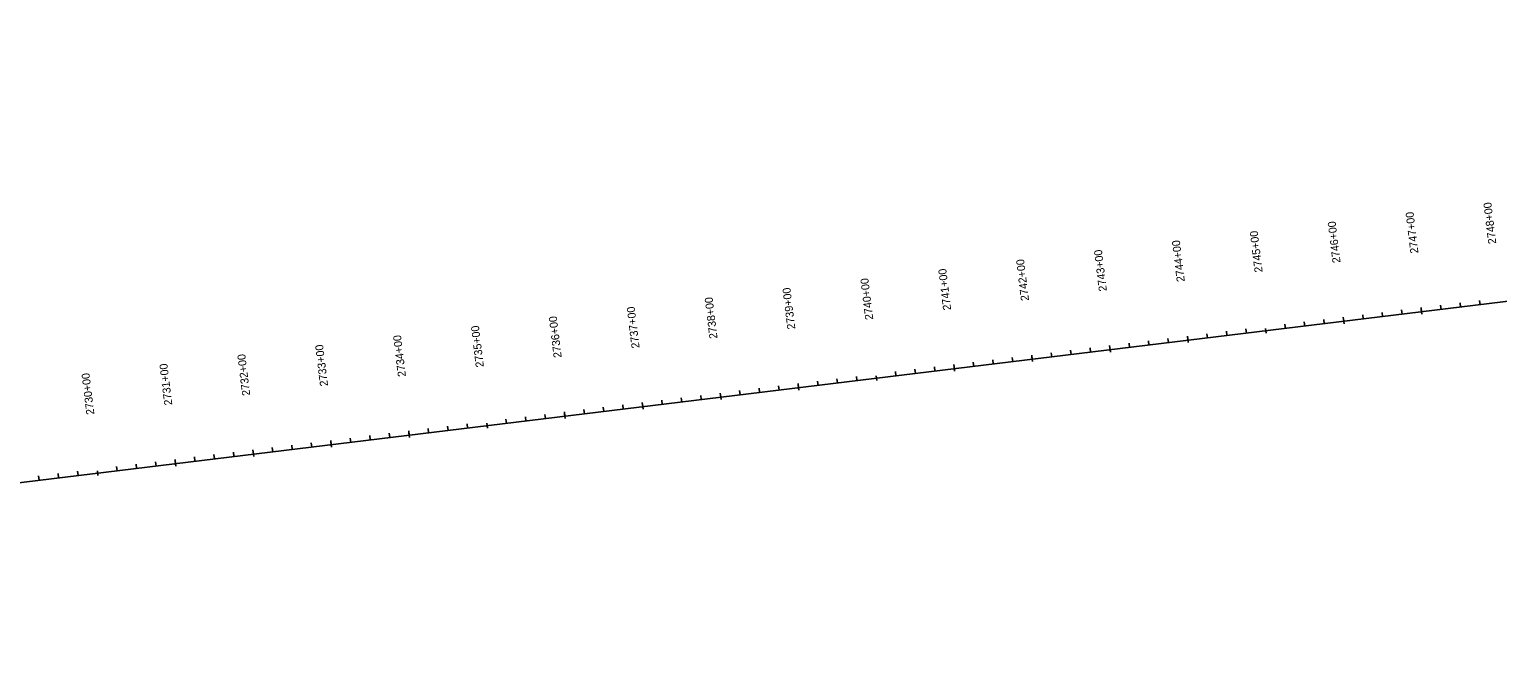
# Model space of a CAD drawing. Extents: x 18432127 to 18439586, y 7649485 to 7650472.
# Drawn here: x 18433981 to 18435853, y 7649488 to 7650289 of the extents above; entities that cross this region are included whole.
import ezdxf

# ---------------------------------------------------------------- set-up
doc = ezdxf.new("R2010")
doc.units = 0
for name, color, linetype in [('MeshTop', 7, 'Continuous'), ('Terrain', 7, 'Continuous'), ('TL_ShoulderTop', 7, 'Continuous')]:
    doc.layers.add(name, color=color, linetype=linetype)

msp = doc.modelspace()

# ---------------------------------------------------------------- linework, layer by layer
at = {"layer": 'MeshTop'}
for p, q in [((18435805.5, 7649934.7), (18435804.8, 7649940.1)), ((18435830.3, 7649937.7), (18435829.7, 7649943.2)), ((18435681.4, 7649919.6), (18435680.8, 7649925)), ((18435706.2, 7649922.6), (18435705.6, 7649928)), ((18435731.1, 7649925.6), (18435730.4, 7649931.1)), ((18435755.5, 7649931.7), (18435756.2, 7649925.6)), ((18435780.7, 7649931.7), (18435780, 7649937.1)), ((18435507.7, 7649898.4), (18435507.1, 7649903.9)), ((18435532.5, 7649901.5), (18435531.9, 7649906.9)), ((18435557, 7649907.5), (18435557.7, 7649901.4)), ((18435582.2, 7649907.5), (18435581.5, 7649912.9)), ((18435607, 7649910.5), (18435606.3, 7649916)), ((18435631.8, 7649913.6), (18435631.1, 7649919)), ((18435656.2, 7649919.6), (18435657, 7649913.5)), ((18435334, 7649877.3), (18435333.3, 7649882.7)), ((18435358.4, 7649883.3), (18435359.2, 7649877.3)), ((18435383.6, 7649883.3), (18435383, 7649888.7)), ((18435408.4, 7649886.3), (18435407.8, 7649891.8)), ((18435433.3, 7649889.4), (18435432.6, 7649894.8)), ((18435457.7, 7649895.4), (18435458.4, 7649889.4)), ((18435482.9, 7649895.4), (18435482.2, 7649900.8)), ((18435185.1, 7649859.1), (18435184.4, 7649864.5)), ((18435209.9, 7649862.2), (18435209.3, 7649867.6)), ((18435234.7, 7649865.2), (18435234.1, 7649870.6)), ((18435259.2, 7649871.2), (18435259.9, 7649865.2)), ((18435284.4, 7649871.2), (18435283.7, 7649876.6)), ((18435309.2, 7649874.2), (18435308.5, 7649879.7)), ((18435036.2, 7649841), (18435035.5, 7649846.4)), ((18435060.6, 7649847), (18435061.4, 7649841)), ((18435085.8, 7649847), (18435085.2, 7649852.5)), ((18435110.6, 7649850.1), (18435110, 7649855.5)), ((18435135.5, 7649853.1), (18435134.8, 7649858.5)), ((18435159.9, 7649859.1), (18435160.7, 7649853.1)), ((18434887.3, 7649822.8), (18434886.6, 7649828.3)), ((18434912.1, 7649825.9), (18434911.5, 7649831.3)), ((18434936.9, 7649828.9), (18434936.3, 7649834.3)), ((18434961.4, 7649835), (18434962.1, 7649828.9)), ((18434986.6, 7649834.9), (18434985.9, 7649840.4)), ((18435011.4, 7649838), (18435010.7, 7649843.4)), ((18434738.4, 7649804.7), (18434737.7, 7649810.1)), ((18434762.8, 7649810.8), (18434763.6, 7649804.7)), ((18434788, 7649810.7), (18434787.4, 7649816.2)), ((18434812.9, 7649813.8), (18434812.2, 7649819.2)), ((18434837.7, 7649816.8), (18434837, 7649822.2)), ((18434862.1, 7649822.9), (18434862.9, 7649816.8)), ((18434589.5, 7649786.6), (18434588.8, 7649792)), ((18434614.3, 7649789.6), (18434613.7, 7649795)), ((18434639.1, 7649792.6), (18434638.5, 7649798)), ((18434663.6, 7649798.7), (18434664.3, 7649792.6)), ((18434688.8, 7649798.7), (18434688.1, 7649804.1)), ((18434713.6, 7649801.7), (18434712.9, 7649807.1)), ((18434415.8, 7649765.4), (18434415.1, 7649770.8)), ((18434440.6, 7649768.4), (18434439.9, 7649773.8)), ((18434465, 7649774.5), (18434465.8, 7649768.4)), ((18434490.2, 7649774.5), (18434489.6, 7649779.9)), ((18434515.1, 7649777.5), (18434514.4, 7649782.9)), ((18434539.9, 7649780.5), (18434539.2, 7649785.9)), ((18434564.3, 7649786.6), (18434565.1, 7649780.5)), ((18434291.7, 7649750.3), (18434291, 7649755.7)), ((18434316.5, 7649753.3), (18434315.9, 7649758.7)), ((18434341.3, 7649756.3), (18434340.7, 7649761.7)), ((18434365.8, 7649762.4), (18434366.5, 7649756.3)), ((18434391, 7649762.4), (18434390.3, 7649767.8)), ((18434118, 7649729.1), (18434117.3, 7649734.5)), ((18434142.8, 7649732.1), (18434142.1, 7649737.5)), ((18434167.3, 7649738.2), (18434168, 7649732.1)), ((18434192.4, 7649738.2), (18434191.8, 7649743.6)), ((18434217.3, 7649741.2), (18434216.6, 7649746.6)), ((18434242.1, 7649744.2), (18434241.4, 7649749.6)), ((18434266.5, 7649750.3), (18434267.3, 7649744.2)), ((18433993.9, 7649714), (18433993.2, 7649719.4)), ((18434018.7, 7649717), (18434018.1, 7649722.4)), ((18434043.5, 7649720), (18434042.9, 7649725.5)), ((18434068, 7649726.1), (18434068.7, 7649720)), ((18434093.2, 7649726.1), (18434092.5, 7649731.5))]:
    msp.add_line(p, q, dxfattribs=at)
at = {"layer": 'Terrain'}
msp.add_line((18432137.1, 7649487.7), (18438712.4, 7650288.9), dxfattribs=at)
at = {"layer": 'TL_ShoulderTop'}
for p, q in [((18435656.6, 7649916.6), (18435655.9, 7649922)), ((18435755.9, 7649928.7), (18435755.2, 7649934.1)), ((18435557, 7649907.5), (18435557.7, 7649901.4)), ((18435358.8, 7649880.3), (18435358.2, 7649885.7)), ((18435458.1, 7649892.4), (18435457.4, 7649897.8)), ((18435259.5, 7649868.2), (18435258.9, 7649873.6)), ((18435060.6, 7649847), (18435061.4, 7649841)), ((18435160.3, 7649856.1), (18435159.6, 7649861.5)), ((18434961.7, 7649831.9), (18434961.1, 7649837.3)), ((18434763.2, 7649807.7), (18434762.6, 7649813.1)), ((18434862.5, 7649819.8), (18434861.8, 7649825.2)), ((18434664, 7649795.6), (18434663.3, 7649801)), ((18434465.4, 7649771.4), (18434464.8, 7649776.9)), ((18434564.3, 7649786.6), (18434565.1, 7649780.5)), ((18434266.9, 7649747.2), (18434266.2, 7649752.7)), ((18434366.2, 7649759.3), (18434365.5, 7649764.8)), ((18434167.6, 7649735.2), (18434167, 7649740.6)), ((18434068, 7649726.1), (18434068.7, 7649720))]:
    msp.add_line(p, q, dxfattribs=at)

# ---------------------------------------------------------------- texts
at = {"layer": 'MeshTop'}
for s, p in [('2747+00', (18435751.9, 7650003.7)), ('2748+00', (18435851.1, 7650015.8)), ('2746+00', (18435652.6, 7649991.6)), ('2744+00', (18435454.1, 7649967.5)), ('2745+00', (18435553.3, 7649979.5)), ('2742+00', (18435255.5, 7649943.3)), ('2743+00', (18435354.8, 7649955.4)), ('2741+00', (18435156.3, 7649931.2)), ('2739+00', (18434957.7, 7649907)), ('2740+00', (18435057, 7649919.1)), ('2738+00', (18434858.5, 7649894.9)), ('2736+00', (18434659.9, 7649870.7)), ('2737+00', (18434759.2, 7649882.8)), ('2735+00', (18434560.7, 7649858.6)), ('2733+00', (18434362.1, 7649834.4)), ('2734+00', (18434461.4, 7649846.5)), ('2732+00', (18434262.9, 7649822.3)), ('2730+00', (18434064.3, 7649798.1)), ('2731+00', (18434163.6, 7649810.2))]:
    msp.add_text(s, height=10.2, rotation=96.947, dxfattribs=at).set_placement(p)
at = {"layer": 'TL_ShoulderTop'}
for s, p in [('2745+00', (18435553.3, 7649979.5)), ('2740+00', (18435057, 7649919.1)), ('2735+00', (18434560.7, 7649858.6)), ('2730+00', (18434064.3, 7649798.1))]:
    msp.add_text(s, height=10.2, rotation=96.947, dxfattribs=at).set_placement(p)

doc.saveas('drawing.dxf')
